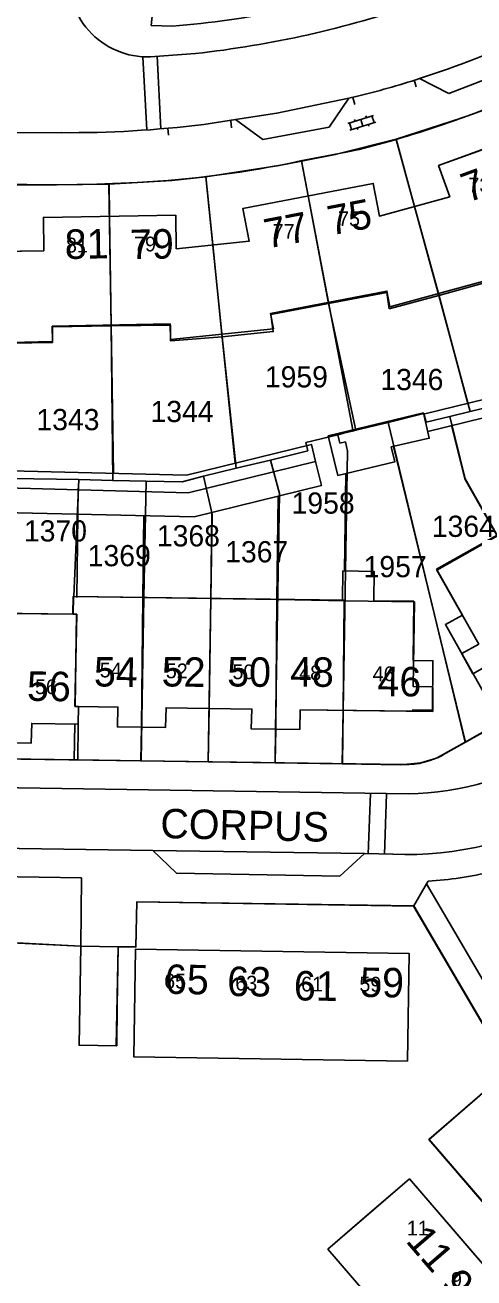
# Model space of a CAD drawing. Extents: x 148816 to 151297, y 399515 to 402500.
# Drawn here: x 150094.5 to 150132.6, y 400288.6 to 400394.8 of the extents above; entities that cross this region are included whole.
import ezdxf

# ---------------------------------------------------------------- set-up
doc = ezdxf.new("R2010")
doc.units = 0
for name, color, linetype in [('B01 Hoofdgebouw  [D] Norm', 7, 'Continuous'), ('B01 Hoofdgebouw  [T] Norm', 7, 'Continuous'), ('B01 hoofgebouw', 7, 'Continuous'), ('B02 Bijgebouw  [D] Norm', 7, 'Continuous'), ('B07 Tussenmuur  [T] Norm', 7, 'Continuous'), ('G01 perceelsgrens', 7, 'Continuous'), ('S02 Open verharding  Norm', 7, 'Continuous'), ('T04 Haag heg  [D] Gem', 7, 'Continuous'), ('V00 Kant verharding algemeen  [D] Norm', 7, 'Continuous'), ('V00 Kant verharding algemeen  [T] Norm', 7, 'Continuous'), ('V00 Kant verharding algemeen secundair  [T] Gem', 7, 'Continuous'), ('Z01 perceelnummer', 7, 'Continuous'), ('Z02 huisnummer', 7, 'Continuous'), ('Z02 Huisnummer  [Tekst] Norm', 7, 'Continuous'), ('Z06 straatnaam', 7, 'Continuous')]:
    doc.layers.add(name, color=color, linetype=linetype)

msp = doc.modelspace()

# ---------------------------------------------------------------- linework, layer by layer
at = {"layer": 'B01 Hoofdgebouw  [D] Norm'}
for p, q in [((150133.72, 400373.21), (150125.44, 400370.95)), ((150106.77, 400369.51), (150096.75, 400369.31)), ((150106.8, 400368.17), (150106.77, 400369.51)), ((150096.75, 400369.31), (150096.78, 400368)), ((150096.78, 400368), (150090.63, 400367.87)), ((150144.73, 400357.35), (150129.41, 400348.69)), ((150131.61, 400344.8), (150129.41, 400348.69)), ((150098.55, 400344.88), (150098.57, 400346.38)), ((150121.56, 400346.06), (150098.57, 400346.38)), ((150127.47, 400345.98), (150124.07, 400346.01)), ((150098.55, 400344.88), (150086.49, 400345.04)), ((150127.47, 400345.98), (150127.42, 400340.95)), ((150098.55, 400344.88), (150098.84, 400344.88))]:
    msp.add_line(p, q, dxfattribs=at)
msp.add_lwpolyline([(150106.8, 400368.17), (150115.55, 400369.07), (150115.3, 400370.38), (150125.18, 400372.28), (150125.44, 400370.95)], dxfattribs=at)
at = {"layer": 'B01 Hoofdgebouw  [T] Norm'}
for p, q in [((150129.57, 400382.93), (150140.13, 400386.77)), ((150130.52, 400380.29), (150129.57, 400382.93)), ((150112.96, 400379.3), (150124.02, 400381.42)), ((150124.02, 400381.42), (150124.55, 400378.65)), ((150124.55, 400378.65), (150130.52, 400380.29)), ((150113.5, 400376.52), (150112.96, 400379.3)), ((150096.01, 400378.53), (150107.26, 400378.71)), ((150096.05, 400375.7), (150096.01, 400378.53)), ((150107.26, 400378.71), (150107.3, 400375.88)), ((150107.3, 400375.88), (150113.5, 400376.52)), ((150090.32, 400375.62), (150096.05, 400375.7)), ((150098.99, 400337.05), (150098.98, 400335.53)), ((150102.34, 400336.99), (150098.99, 400337.05)), ((150102.3, 400335.31), (150102.34, 400336.99)), ((150106.43, 400336.94), (150106.39, 400335.27)), ((150113.72, 400336.82), (150106.43, 400336.94)), ((150113.67, 400335.14), (150113.72, 400336.82)), ((150117.82, 400336.76), (150117.8, 400335.1)), ((150127.38, 400336.65), (150117.82, 400336.76)), ((150095.02, 400335.6), (150094.98, 400333.94)), ((150098.98, 400335.53), (150095.02, 400335.6)), ((150106.39, 400335.27), (150102.3, 400335.31)), ((150117.8, 400335.1), (150113.67, 400335.14)), ((150094.98, 400333.94), (150090.89, 400333.99)), ((150099.04, 400308.32), (150099.2, 400316.72)), ((150099.2, 400316.72), (150102.36, 400316.66)), ((150102.36, 400316.66), (150102.2, 400308.26)), ((150103.7, 400307.32), (150103.84, 400316.46)), ((150103.84, 400316.46), (150127.07, 400316.1)), ((150127.07, 400316.1), (150126.93, 400306.96)), ((150099.04, 400308.32), (150102.2, 400308.26)), ((150126.93, 400306.96), (150103.7, 400307.32)), ((150120.18, 400291), (150127.1, 400296.97)), ((150127.1, 400296.97), (150149.7, 400270.74)), ((150120.18, 400291), (150142.77, 400264.77))]:
    msp.add_line(p, q, dxfattribs=at)
for points in [[(150121.42, 400346.06), (150121.45, 400348.54), (150124.09, 400348.5), (150124.07, 400346.01)], [(150136.01, 400341.67), (150136.84, 400340.22), (150133.38, 400338.27), (150130.15, 400343.99), (150131.61, 400344.8)], [(150127.38, 400336.65), (150127.38, 400336.75), (150129.05, 400336.73), (150129.1, 400340.93), (150127.42, 400340.95)]]:
    msp.add_lwpolyline(points, dxfattribs=at)
at = {"layer": 'B01 hoofgebouw'}
for points in [[(150125.39, 400370.77), (150129.59, 400371.91), (150133.78, 400373.06), (150133.32, 400374.4), (150138.02, 400376.1), (150142.77, 400377.83), (150143.21, 400376.52), (150147.17, 400378.33), (150151.17, 400380.17), (150150.49, 400381.37), (150154.86, 400383.88), (150159.27, 400386.41), (150159.98, 400385.19), (150163.57, 400387.72), (150167.17, 400390.26), (150166.29, 400391.34), (150170.12, 400394.58), (150173.98, 400397.86), (150174.82, 400396.86), (150174.85, 400396.83)], [(150079.84, 400367.68), (150076.28, 400367.61), (150076.13, 400375.36), (150079.07, 400375.4), (150079.01, 400378.23), (150090.26, 400378.45), (150090.32, 400375.62), (150096.05, 400375.7), (150096.01, 400378.53), (150107.26, 400378.71), (150107.3, 400375.88), (150113.5, 400376.52), (150112.96, 400379.3), (150124.02, 400381.42), (150124.55, 400378.65), (150130.52, 400380.29), (150129.57, 400382.93), (150140.13, 400386.77), (150141.1, 400384.1), (150146.77, 400386.7), (150145.36, 400389.16), (150155.11, 400394.77), (150156.52, 400392.33), (150161.61, 400395.91)], [(150125.39, 400370.77), (150125.19, 400372.17), (150120.24, 400371.23), (150115.33, 400370.29), (150115.53, 400368.84), (150111.2, 400368.4), (150106.82, 400368.06), (150106.8, 400369.4), (150101.77, 400369.32), (150096.78, 400369.24), (150096.8, 400367.93), (150093.31, 400367.87), (150090.67, 400367.83), (150090.69, 400366.23), (150087.12, 400366.17), (150087.07, 400369.09), (150084.79, 400369.05), (150079.77, 400368.97), (150079.79, 400367.68)], [(150173.23, 400364.82), (150170.28, 400369.99), (150165.1, 400367.07), (150160.14, 400364.27), (150155.17, 400361.47), (150150.2, 400358.66), (150145.5, 400356.01), (150144.76, 400357.32), (150144.72, 400357.29), (150139.57, 400354.34), (150134.58, 400351.53), (150129.43, 400348.62), (150132.98, 400342.34), (150131.54, 400341.53)], [(150173.23, 400364.82), (150175.66, 400360.45), (150173.65, 400359.33), (150172.83, 400360.78), (150166.49, 400357.2), (150167.31, 400355.75), (150163.74, 400353.74), (150162.91, 400355.18), (150156.54, 400351.6), (150157.37, 400350.15), (150153.81, 400348.11), (150152.98, 400349.56), (150149.54, 400347.62), (150148.79, 400348.95), (150145.89, 400347.29), (150146.72, 400345.84), (150143.15, 400343.8), (150142.33, 400345.26), (150134, 400340.53), (150133.94, 400340.62), (150132.49, 400339.81), (150131.52, 400341.57)], [(150086.49, 400345.04), (150093.13, 400344.92), (150098.52, 400344.88), (150098.55, 400346.38), (150098.6, 400346.38), (150104.54, 400346.29), (150110.23, 400346.2), (150115.91, 400346.11), (150121.63, 400346.01), (150127.54, 400345.92), (150127.43, 400338.73), (150129.1, 400338.71)], [(150129.09, 400338.66), (150129.08, 400336.63), (150117.82, 400336.76), (150117.8, 400335.1), (150113.67, 400335.14), (150113.72, 400336.82), (150106.43, 400336.94), (150106.39, 400335.27), (150102.3, 400335.31), (150102.34, 400336.99), (150098.99, 400337.05), (150098.98, 400335.53), (150095.02, 400335.6), (150094.98, 400333.94), (150090.89, 400333.99), (150090.93, 400335.67), (150081.32, 400335.81), (150081.33, 400335.91), (150079.65, 400335.94), (150079.7, 400337.98), (150081.36, 400337.94), (150081.49, 400345.11), (150086.49, 400345.04)], [(150099.11, 400311.72), (150099.2, 400316.72), (150102.36, 400316.66), (150102.28, 400311.66)], [(150126.93, 400306.96), (150127.07, 400316.1), (150103.84, 400316.46), (150103.7, 400307.32), (150126.93, 400306.96)], [(150102.28, 400311.66), (150102.24, 400308.26), (150099.05, 400308.31), (150099.11, 400311.72)], [(150123.31, 400293.71), (150127.1, 400296.97), (150149.7, 400270.74), (150145.91, 400267.48)], [(150145.91, 400267.48), (150142.75, 400264.8), (150120.18, 400291), (150123.31, 400293.71)]]:
    msp.add_lwpolyline(points, dxfattribs=at)
at = {"layer": 'B02 Bijgebouw  [D] Norm'}
msp.add_lwpolyline([(150128.28, 400361.94), (150120.21, 400360), (150121.02, 400356.64), (150125.85, 400357.79), (150125.55, 400359.06), (150128.78, 400359.8)], close=True, dxfattribs=at)
msp.add_lwpolyline([(150087.66, 400355.72), (150108.32, 400355.18), (150119.12, 400357.82), (150119.62, 400355.78), (150108.82, 400353.14), (150087.6, 400353.62)], dxfattribs=at)
at = {"layer": 'B07 Tussenmuur  [T] Norm'}
for p, q in [((150118.49, 400380.36), (150120.22, 400371.33)), ((150127.54, 400379.47), (150129.57, 400372.07)), ((150101.64, 400378.62), (150101.78, 400369.43)), ((150110.4, 400376.2), (150111.18, 400368.62)), ((150104.35, 400335.29), (150104.45, 400346.3)), ((150110.08, 400336.88), (150110.23, 400346.22)), ((150115.74, 400335.12), (150115.84, 400346.14)), ((150121.47, 400336.72), (150121.56, 400346.06))]:
    msp.add_line(p, q, dxfattribs=at)
msp.add_lwpolyline([(150098.99, 400337.05), (150098.69, 400337.05), (150098.84, 400344.88)], dxfattribs=at)
at = {"layer": 'G01 perceelsgrens'}
for points in [[(150125.97, 400385.16), (150131.58, 400386.97), (150133.79, 400387.77)], [(150117.93, 400383.31), (150120.8, 400383.86), (150125.97, 400385.16)], [(150125.97, 400385.16), (150127.53, 400379.47), (150129.59, 400371.91), (150132.26, 400362.06)], [(150109.81, 400381.98), (150116.03, 400382.94), (150117.93, 400383.31)], [(150117.93, 400383.31), (150118.49, 400380.36), (150120.24, 400371.23), (150122.55, 400360.47)], [(150093.1, 400381.3), (150097.12, 400381.29), (150101.58, 400381.34)], [(150101.58, 400381.34), (150106.91, 400381.67), (150109.81, 400381.98)], [(150101.58, 400381.34), (150101.77, 400369.32), (150101.9, 400356.22)], [(150109.81, 400381.98), (150111.2, 400368.4), (150112.39, 400357.25)], [(150130.53, 400361.63), (150132.26, 400362.06)], [(150132.26, 400362.06), (150135.64, 400362.88)], [(150122.55, 400360.47), (150125.28, 400361.14)], [(150125.28, 400361.14), (150128.32, 400361.89), (150128.51, 400361.15), (150130.53, 400361.63)], [(150125.28, 400361.14), (150131.82, 400334.01)], [(150130.53, 400361.63), (150131.84, 400356.36), (150134.58, 400351.53), (150141.4, 400339.45)], [(150121.01, 400360.1), (150118.29, 400359.43)], [(150121.5, 400360.22), (150121.01, 400360.1)], [(150121.19, 400359.38), (150121.01, 400360.1)], [(150122.24, 400360.4), (150121.5, 400360.22)], [(150122.24, 400360.4), (150122.55, 400360.47)], [(150118.29, 400359.43), (150118.46, 400358.72)], [(150121.19, 400359.38), (150121.66, 400359.49)], [(150121.4, 400332.17), (150121.48, 400336.69), (150121.83, 400358.71), (150121.66, 400359.49)], [(150112.39, 400357.25), (150115.29, 400357.95)], [(150115.29, 400357.95), (150118.46, 400358.72)], [(150115.29, 400357.95), (150116.06, 400355.12), (150115.73, 400335.12), (150115.69, 400332.25)], [(150109.61, 400356.57), (150112.39, 400357.25)], [(150093.31, 400356.37), (150099.01, 400356.29)], [(150098.93, 400332.51), (150098.98, 400335.52), (150098.99, 400337.05), (150098.7, 400337.05), (150098.82, 400344.88), (150098.52, 400344.88), (150098.55, 400346.38), (150098.6, 400346.38), (150099.01, 400356.29)], [(150099.01, 400356.29), (150101.9, 400356.22)], [(150101.9, 400356.22), (150104.75, 400356.17)], [(150104.32, 400332.42), (150104.54, 400346.29), (150104.75, 400356.17)], [(150104.75, 400356.17), (150107.81, 400356.11), (150109.61, 400356.57)], [(150109.61, 400356.57), (150110.36, 400353.35), (150110.23, 400346.2), (150110.01, 400332.34)], [(150131.82, 400334.01), (150141.4, 400339.45)], [(150121.4, 400332.17), (150126.33, 400332.1), (150128.06, 400332.25), (150129.39, 400332.65), (150131.82, 400334.01)], [(150092.93, 400332.6), (150098.93, 400332.51)], [(150098.93, 400332.51), (150104.32, 400332.42)], [(150104.32, 400332.42), (150110.01, 400332.34)], [(150110.01, 400332.34), (150115.69, 400332.25)], [(150115.69, 400332.25), (150121.4, 400332.17)], [(150167.04, 400251.21), (150135.49, 400220.71), (150118.87, 400237.89), (150117.21, 400236.42), (150078.08, 400281.75), (150079.99, 400317.72), (150092.08, 400317.06), (150099.2, 400316.7), (150102.37, 400316.66), (150103.87, 400316.63), (150103.95, 400320.48), (150127.45, 400320.1), (150135.59, 400306.23), (150128.76, 400300.32), (150152.25, 400273.02), (150149.7, 400270.74), (150148.82, 400269.98), (150167.04, 400251.21)]]:
    msp.add_lwpolyline(points, dxfattribs=at)
at = {"layer": 'S02 Open verharding  Norm'}
for p, q in [((150121.87, 400386.5), (150124.06, 400387.19)), ((150122.19, 400385.98), (150122.01, 400386.55)), ((150122.05, 400385.93), (150124.24, 400386.62)), ((150122.44, 400386.84), (150122.49, 400386.7)), ((150122.96, 400386.85), (150123.14, 400386.27)), ((150123.4, 400387.14), (150123.44, 400387)), ((150123.62, 400386.42), (150123.66, 400386.28)), ((150124.1, 400386.57), (150123.92, 400387.15)), ((150122.67, 400386.13), (150122.71, 400385.98))]:
    msp.add_line(p, q, dxfattribs=at)
at = {"layer": 'T04 Haag heg  [D] Gem'}
for p, q in [((150127.54, 400379.47), (150125.98, 400385.15)), ((150118.49, 400380.36), (150117.92, 400383.33)), ((150101.64, 400378.62), (150101.59, 400381.39)), ((150110.4, 400376.2), (150109.8, 400381.99)), ((150129.57, 400372.07), (150132.05, 400362.75)), ((150120.22, 400371.33), (150122.29, 400360.5)), ((150101.78, 400369.41), (150101.98, 400356.83)), ((150111.18, 400368.62), (150112.31, 400357.69)), ((150130.68, 400360.87), (150131.79, 400356.35)), ((150125.74, 400359.1), (150131.86, 400334.02)), ((150121.71, 400356.8), (150121.59, 400348.54)), ((150098.96, 400355.56), (150098.86, 400346.29)), ((150131.79, 400356.35), (150134.51, 400351.57)), ((150115.96, 400354.88), (150115.84, 400346.14)), ((150110.33, 400353.5), (150110.23, 400346.22)), ((150104.53, 400353.23), (150104.45, 400346.3)), ((150110.01, 400332.36), (150110.08, 400336.88)), ((150121.41, 400332.2), (150121.47, 400336.72)), ((150098.63, 400332.52), (150098.67, 400335.54)), ((150104.3, 400332.44), (150104.35, 400335.29)), ((150115.7, 400332.28), (150115.74, 400335.12))]:
    msp.add_line(p, q, dxfattribs=at)
at = {"layer": 'V00 Kant verharding algemeen  [D] Norm'}
msp.add_lwpolyline([(150119.12, 400357.82), (150118.77, 400359.27), (150108.16, 400356.68), (150081.74, 400357.32)], dxfattribs=at)
at = {"layer": 'V00 Kant verharding algemeen  [T] Norm'}
for p, q in [((150106.79, 400409.77), (150105.16, 400394.8)), ((150105.16, 400394.8), (150106.97, 400394.76)), ((150108.92, 400392.43), (150105.47, 400392.18)), ((150135.89, 400391.13), (150130.45, 400389.05)), ((150127.5, 400390.2), (150127.67, 400389.62)), ((150130.45, 400389.05), (150127.96, 400390.31)), ((150121.94, 400388.65), (150120.29, 400386.2)), ((150122.56, 400388.78), (150121.94, 400388.65)), ((150122.29, 400388.7), (150122.45, 400388.12)), ((150109.63, 400386.42), (150112.33, 400386.84)), ((150111.93, 400386.72), (150112, 400386.12)), ((150114.64, 400385.13), (150112.33, 400386.84)), ((150086.5, 400385.77), (150097.54, 400385.72)), ((150106.59, 400386.11), (150106.65, 400385.51)), ((150120.29, 400386.2), (150114.64, 400385.13)), ((150122.83, 400384.28), (150121.73, 400384.06)), ((150125.38, 400384.97), (150122.83, 400384.28)), ((150121.73, 400384.06), (150117.85, 400383.32)), ((150097.17, 400381.3), (150092.02, 400381.36)), ((150100.55, 400381.35), (150097.17, 400381.3)), ((150103.99, 400381.5), (150100.55, 400381.35)), ((150142.88, 400365.42), (150128.3, 400361.83)), ((150143.43, 400364.01), (150128.66, 400360.37)), ((150129.93, 400332.93), (150176.88, 400359.41)), ((150070.39, 400332.91), (150126.66, 400332.13)), ((150082.93, 400330.32), (150126.98, 400329.64)), ((150083.83, 400325.16), (150105.3, 400324.83)), ((150125.7, 400324.52), (150123.27, 400324.56)), ((150099.24, 400322.5), (150099.2, 400316.72)), ((150127.46, 400320.13), (150128.55, 400321.99)), ((150128.55, 400321.99), (150128.7, 400322.23)), ((150103.94, 400320.48), (150103.86, 400316.65)), ((150127.46, 400320.13), (150103.94, 400320.48)), ((150135.6, 400306.25), (150127.46, 400320.13)), ((150092.08, 400317.09), (150099.2, 400316.72)), ((150103.86, 400316.65), (150102.36, 400316.66)), ((150128.77, 400300.32), (150135.6, 400306.25)), ((150154.17, 400270.84), (150128.77, 400300.32))]:
    msp.add_line(p, q, dxfattribs=at)
msp.add_lwpolyline([(150123.27, 400324.56), (150121.2, 400322.66), (150107.32, 400322.89), (150105.3, 400324.83)], dxfattribs=at)
for centre, radius, start, end in [((150099.52, 400477.79), 85.89, 282.7735, 295.6066), ((150104.84, 400398.81), 6.66, 174.2585, 275.4267), ((150101.13, 400471.25), 76.71, 274.3642, 288.9149), ((150098.76, 400482.89), 91.03, 276.4108, 282.5332), ((150092.23, 400497.21), 117.04, 286.4542, 294.7996), ((150103.42, 400466.63), 80.17, 283.8143, 287.8267), ((150098.35, 400476.57), 90.85, 269.492, 277.1353), ((150099.53, 400469.17), 87.78, 272.9139, 282.0478), ((150126.68, 400354.17), 24.53, 270.6953, 302.3256), ((150126.8, 400338.62), 6.5, 268.7264, 298.7681), ((150126.95, 400352.53), 28.04, 267.4579, 300.2902), ((150127.08, 400351.76), 29.57, 273.1311, 283.7228)]:
    msp.add_arc(centre, radius, start, end, dxfattribs=at)
at = {"layer": 'V00 Kant verharding algemeen secundair  [T] Gem'}
for p, q in [((150104.79, 400385.95), (150104.47, 400392.16)), ((150106, 400386.04), (150105.68, 400392.2)), ((150127.5, 400390.2), (150127.67, 400389.62)), ((150115.84, 400387.38), (150121.94, 400388.65)), ((150122.29, 400388.7), (150122.45, 400388.12)), ((150111.93, 400386.72), (150112, 400386.12)), ((150115.84, 400387.38), (150112.33, 400386.84)), ((150106.59, 400386.11), (150106.65, 400385.51)), ((150123.78, 400329.69), (150123.6, 400324.52)), ((150125.16, 400329.64), (150124.99, 400324.5)), ((150105.3, 400324.83), (150123.27, 400324.56)), ((150099.24, 400322.5), (150084.03, 400322.73)), ((150128.55, 400321.99), (150135.33, 400310.43))]:
    msp.add_line(p, q, dxfattribs=at)
msp.add_arc((150103.42, 400466.63), 80.17, 287.8267, 294.967, dxfattribs=at)

# ---------------------------------------------------------------- texts
at = {"layer": 'Z01 perceelnummer'}
for s, p in [('1959', (150114.82, 400364.11)), ('1346', (150124.63, 400363.88)), ('1344', (150105.11, 400361.17)), ('1343', (150095.42, 400360.48)), ('1958', (150117.09, 400353.4)), ('1370', (150094.36, 400351.04)), ('1368', (150105.65, 400350.62)), ('1364', (150129, 400351.43)), ('1369', (150099.78, 400348.94)), ('1367', (150111.45, 400349.27)), ('1957', (150123.21, 400348.01))]:
    msp.add_text(s, height=1.8, dxfattribs=at).set_placement(p)
at = {"layer": 'Z02 huisnummer'}
for s, rotation, p in [('73', 19.9929, (150132.06, 400379.77)), ('75', 10.8379, (150120.41, 400376.99)), ('77', 10.8379, (150115.02, 400375.88)), ('81', 0.9739, (150097.85, 400375)), ('79', 0.9739, (150103.39, 400374.99)), ('54', 359.1979, (150100.29, 400338.75)), ('52', 359.1979, (150106.05, 400338.75)), ('50', 359.1979, (150111.61, 400338.75)), ('48', 359.1979, (150116.95, 400338.75)), ('56', 359.1979, (150094.61, 400337.53)), ('46', 359.3698, (150124.37, 400337.93)), ('65', 359.0833, (150106.32, 400312.67)), ('63', 359.0833, (150111.61, 400312.49)), ('61', 359.0833, (150117.27, 400312.12)), ('59', 359.0833, (150122.9, 400312.41)), ('11', 310.7442, (150126.71, 400291.67)), ('9', 310.7442, (150129.65, 400287.97))]:
    msp.add_text(s, height=2.5, rotation=rotation, dxfattribs=at).set_placement(p)
at = {"layer": 'Z02 Huisnummer  [Tekst] Norm'}
for s, p in [('73', (150132.11, 400380.66)), ('75', (150121.04, 400377.79)), ('77', (150115.49, 400376.73)), ('81', (150097.93, 400375.56)), ('79', (150103.71, 400375.65)), ('54', (150100.8, 400339.51)), ('52', (150106.41, 400339.44)), ('50', (150112.07, 400339.36)), ('48', (150117.74, 400339.28)), ('46', (150123.98, 400339.19)), ('56', (150095.3, 400338.09)), ('65', (150106.27, 400313.12)), ('63', (150112.31, 400312.95)), ('61', (150117.9, 400312.87)), ('59', (150122.85, 400312.86)), ('11', (150126.88, 400292.17)), ('9', (150130.63, 400287.8))]:
    msp.add_text(s, height=1.25, dxfattribs=at).set_placement(p)
at = {"layer": 'Z06 straatnaam'}
msp.add_text('CORPUS', height=2.5, rotation=358.7397, dxfattribs=at).set_placement((150105.93, 400325.88))

doc.saveas('drawing.dxf')
